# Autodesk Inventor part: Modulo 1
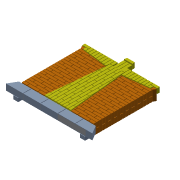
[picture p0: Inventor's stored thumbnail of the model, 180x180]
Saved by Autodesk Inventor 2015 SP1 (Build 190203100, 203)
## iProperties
Created: 2015-04
Part Number: Modulo 1
Material: Generic
Document SubType Name: Modeling
Designer: treina2
Density: 1 g/cm^3
Appearance: Default
Author: treina2
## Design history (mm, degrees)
sketch "Sketch1"
  geometry: L1 (1091.806, 200)-(1091.806, 440) reference; L2 (1091.806, 440)-(1033.806, 440) reference; L3 (1033.806, 440)-(1033.806, 200) reference; L4 (1033.806, 200)-(1091.806, 200) reference; L5 (1159.806, 200)-(1159.806, 315) reference; L6 (1159.806, 315)-(1101.806, 315) reference; L7 (1101.806, 315)-(1101.806, 200) reference; L8 (1101.806, 200)-(1159.806, 200) reference; L9 (1227.806, 200)-(1227.806, 440) reference; L10 (1227.806, 440)-(1169.806, 440) reference; L11 (1169.806, 440)-(1169.806, 200) reference; L12 (1169.806, 200)-(1227.806, 200) reference; L13 (1024, 200)-(1024, 315) reference; L14 (1024, 315)-(966, 315) reference; L15 (966, 315)-(966, 200) reference; L16 (966, 200)-(1024, 200) reference; L17 (1169.806, 1464.632)-(1169.806, 1450) reference; L18 (1169.806, 1450)-(1171.263, 1450) reference; L19 (1284.348, 315)-(1237.806, 315) reference; L20 (1237.806, 315)-(1237.806, 200) reference; L21 (1237.806, 200)-(1295.806, 200) reference; L22 (1259.439, 565)-(1283.351, 325) reference; L23 (1259.439, 565)-(1237.806, 565) reference; L24 (1237.806, 565)-(1237.806, 325) reference; L25 (1237.806, 325)-(1283.351, 325) reference; L26 (1169.806, 1565)-(1177.128, 1492) reference; L27 (1237.806, 1498.938)-(1295.806, 1505.57) reference; L28 (1295.806, 1505.57)-(1295.806, 1686) reference; L29 (1295.806, 1686)-(1237.806, 1686) reference; L30 (1237.806, 1686)-(1237.806, 1498.938) reference; L31 (1159.806, 325)-(1159.806, 565) reference; L32 (1159.806, 565)-(1101.806, 565) reference; L33 (1101.806, 565)-(1101.806, 325) reference; L34 (1101.806, 325)-(1159.806, 325) reference; L35 (1703.806, 1552.224)-(1703.806, 1686) reference; L36 (1703.806, 1686)-(1645.806, 1686) reference; L37 (1645.806, 1686)-(1645.806, 1545.592) reference; L38 (1024, 325)-(1024, 565) reference; L39 (1024, 565)-(966, 565) reference; L40 (966, 565)-(966, 325) reference; L41 (966, 325)-(1024, 325) reference; L42 (1091.806, 450)-(1091.806, 690) reference; L43 (1091.806, 690)-(1033.806, 690) reference; L44 (1033.806, 690)-(1033.806, 450) reference; L45 (1033.806, 450)-(1091.806, 450) reference; L46 (1227.806, 450)-(1227.806, 690) reference; L47 (1227.806, 690)-(1169.806, 690) reference; L48 (1169.806, 690)-(1169.806, 450) reference; L49 (1169.806, 450)-(1227.806, 450) reference; L50 (1159.806, 575)-(1159.806, 815) reference; L51 (1159.806, 815)-(1101.806, 815) reference; L52 (1101.806, 815)-(1101.806, 575) reference; L53 (1101.806, 575)-(1159.806, 575) reference; L54 (1237.806, 782.132)-(1237.806, 575) reference; L55 (1237.806, 575)-(1258.443, 575) reference; L56 (1024, 575)-(1024, 815) reference; L57 (1024, 815)-(966, 815) reference; L58 (966, 815)-(966, 575) reference; L59 (966, 575)-(1024, 575) reference; L60 (1091.806, 700)-(1091.806, 940) reference; L61 (1091.806, 940)-(1033.806, 940) reference; L62 (1033.806, 940)-(1033.806, 700) reference; L63 (1033.806, 700)-(1091.806, 700) reference; L64 (1227.806, 700)-(1227.806, 882.5) reference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; 1 further point
  constraints: 1754 end point, 397 horizontal, 367 vertical, 18 point on line, 953 other
workplane "Work Plane1"
sketch "Sketch2"
  geometry: L1 (1990, 0)-(1600, 0) reference; L2 (1990, 0)-(1880.303, 190) reference; L3 (1765, 190)-(1880.303, 190) reference; L4 (1600, 190)-(1880.303, 190) reference; L5 (1600, 0)-(1600, 190) reference; L6 (1590, 190)-(1590, 0) reference; L7 (1200, 190)-(1590, 190) reference; L8 (1590, 0)-(1200, 0) reference; L9 (1200, 0)-(1200, 190) reference; L10 (1190, 190)-(1190, 0) reference; L11 (1190, 0)-(800, 0) reference; L12 (800, 190)-(1190, 190) reference; L13 (800, 0)-(800, 190) reference; L14 (790, 190)-(790, 0) reference; L15 (400, 190)-(790, 190) reference; L16 (790, 0)-(400, 0) reference; L17 (400, 0)-(400, 190) reference; L18 (390, 190)-(390, 0) reference; L19 (109.697, 190)-(390, 190) reference; L20 (390, 0)-(0, 0) reference; L21 (0, 0)-(109.697, 190) reference; 1 further point
extrude "Extrusion1" new body sketch "Sketch2" distance "d2" = 140 (= BLOCO_PADRAO_LARG); taper "d3" = 0 deg
extrude "Extrusion2" new body sketch "Sketch2" distance "d4" = 140 (= BLOCO_PADRAO_LARG); taper "d5" = 0 deg
extrude "Extrusion3" new body sketch "Sketch2" distance "d6" = 140 (= BLOCO_PADRAO_LARG); taper "d7" = 0 deg
extrude "Extrusion4" new body sketch "Sketch2" distance "d8" = 140 (= BLOCO_PADRAO_LARG); taper "d9" = 0 deg
extrude "Extrusion5" new body sketch "Sketch2" distance "d10" = 140 (= BLOCO_PADRAO_LARG); taper "d11" = 0 deg
extrude "Extrusion6" new body sketch "Sketch1" distance "d12" = 240 (= TIJOLO_PADRAO_COMP); taper "d13" = 0 deg
extrude "Extrusion7" new body sketch "Sketch1" distance "d14" = 240 (= TIJOLO_PADRAO_COMP); taper "d15" = 0 deg
extrude "Extrusion8" new body sketch "Sketch1" distance "d16" = 115 (= TIJOLO_PADRAO_LARG); taper "d17" = 0 deg
extrude "Extrusion9" new body sketch "Sketch1" distance "d18" = 115 (= TIJOLO_PADRAO_LARG); taper "d19" = 0 deg
extrude "Extrusion10" new body sketch "Sketch1" distance "d20" = 115 (= TIJOLO_PADRAO_LARG); taper "d21" = 0 deg
extrude "Extrusion11" new body sketch "Sketch1" distance "d22" = 115 (= TIJOLO_PADRAO_LARG); taper "d23" = 0 deg
extrude "Extrusion12" new body sketch "Sketch1" distance "d24" = 115 (= TIJOLO_PADRAO_LARG); taper "d25" = 0 deg
extrude "Extrusion13" new body sketch "Sketch1" distance "d26" = 240 (= TIJOLO_PADRAO_COMP); taper "d27" = 0 deg
extrude "Extrusion14" new body sketch "Sketch1" distance "d28" = 115 (= TIJOLO_PADRAO_LARG); taper "d29" = 0 deg
extrude "Extrusion15" new body sketch "Sketch1" distance "d30" = 115 (= TIJOLO_PADRAO_LARG); taper "d31" = 0 deg
extrude "Extrusion16" new body sketch "Sketch1" distance "d32" = 115 (= TIJOLO_PADRAO_LARG); taper "d33" = 0 deg
extrude "Extrusion17" new body sketch "Sketch1" distance "d34" = 115 (= TIJOLO_PADRAO_LARG); taper "d35" = 0 deg
extrude "Extrusion18" new body sketch "Sketch1" distance "d36" = 115 (= TIJOLO_PADRAO_LARG); taper "d37" = 0 deg
extrude "Extrusion19" new body sketch "Sketch1" distance "d38" = 115 (= TIJOLO_PADRAO_LARG); taper "d39" = 0 deg
extrude "Extrusion20" new body sketch "Sketch1" distance "d40" = 115 (= TIJOLO_PADRAO_LARG); taper "d41" = 0 deg
extrude "Extrusion21" new body sketch "Sketch1" distance "d42" = 115 (= TIJOLO_PADRAO_LARG); taper "d43" = 0 deg
extrude "Extrusion22" new body sketch "Sketch1" distance "d44" = 115 (= TIJOLO_PADRAO_LARG); taper "d45" = 0 deg
extrude "Extrusion23" new body sketch "Sketch1" distance "d46" = 115 (= TIJOLO_PADRAO_LARG); taper "d47" = 0 deg
extrude "Extrusion24" new body sketch "Sketch1" distance "d48" = 240 (= TIJOLO_PADRAO_COMP); taper "d49" = 0 deg
extrude "Extrusion25" new body sketch "Sketch1" distance "d50" = 115 (= TIJOLO_PADRAO_LARG); taper "d51" = 0 deg
extrude "Extrusion26" new body sketch "Sketch1" distance "d52" = 115 (= TIJOLO_PADRAO_LARG); taper "d53" = 0 deg
extrude "Extrusion27" new body sketch "Sketch1" distance "d54" = 240 (= TIJOLO_PADRAO_COMP); taper "d55" = 0 deg
extrude "Extrusion28" new body sketch "Sketch1" distance "d56" = 115 (= TIJOLO_PADRAO_LARG); taper "d57" = 0 deg
extrude "Extrusion29" new body sketch "Sketch1" distance "d58" = 115 (= TIJOLO_PADRAO_LARG); taper "d59" = 0 deg
extrude "Extrusion30" new body sketch "Sketch1" distance "d60" = 115 (= TIJOLO_PADRAO_LARG); taper "d61" = 0 deg
extrude "Extrusion31" new body sketch "Sketch1" distance "d62" = 115 (= TIJOLO_PADRAO_LARG); taper "d63" = 0 deg
extrude "Extrusion32" new body sketch "Sketch1" distance "d64" = 115 (= TIJOLO_PADRAO_LARG); taper "d65" = 0 deg
extrude "Extrusion33" new body sketch "Sketch1" distance "d66" = 115 (= TIJOLO_PADRAO_LARG); taper "d67" = 0 deg
extrude "Extrusion34" new body sketch "Sketch1" distance "d68" = 115 (= TIJOLO_PADRAO_LARG); taper "d69" = 0 deg
extrude "Extrusion35" new body sketch "Sketch1" distance "d70" = 115 (= TIJOLO_PADRAO_LARG); taper "d71" = 0 deg
extrude "Extrusion36" new body sketch "Sketch1" distance "d72" = 240 (= TIJOLO_PADRAO_COMP); taper "d73" = 0 deg
extrude "Extrusion37" new body sketch "Sketch1" distance "d74" = 115 (= TIJOLO_PADRAO_LARG); taper "d75" = 0 deg
extrude "Extrusion38" new body sketch "Sketch1" distance "d76" = 115 (= TIJOLO_PADRAO_LARG); taper "d77" = 0 deg
extrude "Extrusion39" new body sketch "Sketch1" distance "d78" = 115 (= TIJOLO_PADRAO_LARG); taper "d79" = 0 deg
extrude "Extrusion40" new body sketch "Sketch1" distance "d80" = 115 (= TIJOLO_PADRAO_LARG); taper "d81" = 0 deg
extrude "Extrusion41" new body sketch "Sketch1" distance "d82" = 115 (= TIJOLO_PADRAO_LARG); taper "d83" = 0 deg
extrude "Extrusion42" new body sketch "Sketch1" distance "d84" = 115 (= TIJOLO_PADRAO_LARG); taper "d85" = 0 deg
extrude "Extrusion43" new body sketch "Sketch1" distance "d86" = 115 (= TIJOLO_PADRAO_LARG); taper "d87" = 0 deg
extrude "Extrusion44" new body sketch "Sketch1" distance "d88" = 240 (= TIJOLO_PADRAO_COMP); taper "d89" = 0 deg
extrude "Extrusion45" new body sketch "Sketch1" distance "d90" = 240 (= TIJOLO_PADRAO_COMP); taper "d91" = 0 deg
extrude "Extrusion46" new body sketch "Sketch1" distance "d92" = 240 (= TIJOLO_PADRAO_COMP); taper "d93" = 0 deg
extrude "Extrusion47" new body sketch "Sketch1" distance "d94" = 240 (= TIJOLO_PADRAO_COMP); taper "d95" = 0 deg
extrude "Extrusion48" new body sketch "Sketch1" distance "d96" = 240 (= TIJOLO_PADRAO_COMP); taper "d97" = 0 deg
extrude "Extrusion49" new body sketch "Sketch1" distance "d98" = 115 (= TIJOLO_PADRAO_LARG); taper "d99" = 0 deg
extrude "Extrusion50" new body sketch "Sketch1" distance "d100" = 115 (= TIJOLO_PADRAO_LARG); taper "d101" = 0 deg
extrude "Extrusion51" new body sketch "Sketch1" distance "d102" = 115 (= TIJOLO_PADRAO_LARG); taper "d103" = 0 deg
extrude "Extrusion52" new body sketch "Sketch1" distance "d104" = 115 (= TIJOLO_PADRAO_LARG); taper "d105" = 0 deg
extrude "Extrusion53" new body sketch "Sketch1" distance "d106" = 115 (= TIJOLO_PADRAO_LARG); taper "d107" = 0 deg
extrude "Extrusion54" new body sketch "Sketch1" distance "d108" = 115 (= TIJOLO_PADRAO_LARG); taper "d109" = 0 deg
extrude "Extrusion55" new body sketch "Sketch1" distance "d110" = 115 (= TIJOLO_PADRAO_LARG); taper "d111" = 0 deg
extrude "Extrusion56" new body sketch "Sketch1" distance "d112" = 115 (= TIJOLO_PADRAO_LARG); taper "d113" = 0 deg
extrude "Extrusion57" new body sketch "Sketch1" distance "d114" = 115 (= TIJOLO_PADRAO_LARG); taper "d115" = 0 deg
extrude "Extrusion58" new body sketch "Sketch1" distance "d116" = 115 (= TIJOLO_PADRAO_LARG); taper "d117" = 0 deg
extrude "Extrusion59" new body sketch "Sketch1" distance "d118" = 115 (= TIJOLO_PADRAO_LARG); taper "d119" = 0 deg
extrude "Extrusion60" new body sketch "Sketch1" distance "d120" = 115 (= TIJOLO_PADRAO_LARG); taper "d121" = 0 deg
extrude "Extrusion61" new body sketch "Sketch1" distance "d122" = 115 (= TIJOLO_PADRAO_LARG); taper "d123" = 0 deg
extrude "Extrusion62" new body sketch "Sketch1" distance "d124" = 115 (= TIJOLO_PADRAO_LARG); taper "d125" = 0 deg
extrude "Extrusion63" new body sketch "Sketch1" distance "d126" = 115 (= TIJOLO_PADRAO_LARG); taper "d127" = 0 deg
extrude "Extrusion64" new body sketch "Sketch1" distance "d128" = 115 (= TIJOLO_PADRAO_LARG); taper "d129" = 0 deg
extrude "Extrusion65" new body sketch "Sketch1" distance "d130" = 115 (= TIJOLO_PADRAO_LARG); taper "d131" = 0 deg
extrude "Extrusion66" new body sketch "Sketch1" distance "d132" = 115 (= TIJOLO_PADRAO_LARG); taper "d133" = 0 deg
extrude "Extrusion67" new body sketch "Sketch1" distance "d134" = 115 (= TIJOLO_PADRAO_LARG); taper "d135" = 0 deg
extrude "Extrusion68" new body sketch "Sketch1" distance "d136" = 115 (= TIJOLO_PADRAO_LARG); taper "d137" = 0 deg
extrude "Extrusion69" new body sketch "Sketch1" distance "d138" = 240 (= TIJOLO_PADRAO_COMP); taper "d139" = 0 deg
extrude "Extrusion70" new body sketch "Sketch1" distance "d140" = 240 (= TIJOLO_PADRAO_COMP); taper "d141" = 0 deg
extrude "Extrusion71" new body sketch "Sketch1" distance "d142" = 240 (= TIJOLO_PADRAO_COMP); taper "d143" = 0 deg
extrude "Extrusion72" new body sketch "Sketch1" distance "d144" = 240 (= TIJOLO_PADRAO_COMP); taper "d145" = 0 deg
extrude "Extrusion73" new body sketch "Sketch1" distance "d146" = 240 (= TIJOLO_PADRAO_COMP); taper "d147" = 0 deg
extrude "Extrusion74" new body sketch "Sketch1" distance "d148" = 240 (= TIJOLO_PADRAO_COMP); taper "d149" = 0 deg
extrude "Extrusion75" new body sketch "Sketch1" distance "d150" = 240 (= TIJOLO_PADRAO_COMP); taper "d151" = 0 deg
extrude "Extrusion76" new body sketch "Sketch1" distance "d152" = 240 (= TIJOLO_PADRAO_COMP); taper "d153" = 0 deg
extrude "Extrusion77" new body sketch "Sketch1" distance "d154" = 240 (= TIJOLO_PADRAO_COMP); taper "d155" = 0 deg
extrude "Extrusion78" new body sketch "Sketch1" distance "d156" = 115 (= TIJOLO_PADRAO_LARG); taper "d157" = 0 deg
extrude "Extrusion79" new body sketch "Sketch1" distance "d158" = 115 (= TIJOLO_PADRAO_LARG); taper "d159" = 0 deg
extrude "Extrusion80" new body sketch "Sketch1" distance "d160" = 115 (= TIJOLO_PADRAO_LARG); taper "d161" = 0 deg
extrude "Extrusion81" new body sketch "Sketch1" distance "d162" = 115 (= TIJOLO_PADRAO_LARG); taper "d163" = 0 deg
extrude "Extrusion82" new body sketch "Sketch1" distance "d164" = 115 (= TIJOLO_PADRAO_LARG); taper "d165" = 0 deg
extrude "Extrusion83" new body sketch "Sketch1" distance "d166" = 115 (= TIJOLO_PADRAO_LARG); taper "d167" = 0 deg
extrude "Extrusion84" new body sketch "Sketch1" distance "d168" = 115 (= TIJOLO_PADRAO_LARG); taper "d169" = 0 deg
extrude "Extrusion85" new body sketch "Sketch1" distance "d170" = 115 (= TIJOLO_PADRAO_LARG); taper "d171" = 0 deg
extrude "Extrusion86" new body sketch "Sketch1" distance "d172" = 115 (= TIJOLO_PADRAO_LARG); taper "d173" = 0 deg
extrude "Extrusion87" new body sketch "Sketch1" distance "d174" = 115 (= TIJOLO_PADRAO_LARG); taper "d175" = 0 deg
extrude "Extrusion88" new body sketch "Sketch1" distance "d176" = 115 (= TIJOLO_PADRAO_LARG); taper "d177" = 0 deg
extrude "Extrusion89" new body sketch "Sketch1" distance "d178" = 115 (= TIJOLO_PADRAO_LARG); taper "d179" = 0 deg
extrude "Extrusion90" new body sketch "Sketch1" distance "d180" = 115 (= TIJOLO_PADRAO_LARG); taper "d181" = 0 deg
pattern_linear "Rectangular Pattern1" dims "d184" = 136 (= 2 x TIJOLO_PADRAO_PROF + 2 x GAP)
pattern_linear "Rectangular Pattern2" dims "d187" = 136 (= 2 x TIJOLO_PADRAO_PROF + 2 x GAP)
pattern_linear "Rectangular Pattern3" dims "d190" = 136 (= 2 x TIJOLO_PADRAO_PROF + 2 x GAP)
extrude "Extrusion91" new body sketch "Sketch1" distance "d191" = 115 (= TIJOLO_PADRAO_LARG); taper "d192" = 0 deg
extrude "Extrusion92" new body sketch "Sketch1" distance "d193" = 115 (= TIJOLO_PADRAO_LARG); taper "d194" = 0 deg
extrude "Extrusion93" new body sketch "Sketch1" distance "d195" = 115 (= TIJOLO_PADRAO_LARG); taper "d196" = 0 deg
extrude "Extrusion94" new body sketch "Sketch1" distance "d197" = 115 (= TIJOLO_PADRAO_LARG); taper "d198" = 0 deg
extrude "Extrusion95" new body sketch "Sketch1" distance "d199" = 115 (= TIJOLO_PADRAO_LARG); taper "d200" = 0 deg
extrude "Extrusion96" new body sketch "Sketch1" distance "d201" = 115 (= TIJOLO_PADRAO_LARG); taper "d202" = 0 deg
extrude "Extrusion97" new body sketch "Sketch1" distance "d203" = 115 (= TIJOLO_PADRAO_LARG); taper "d204" = 0 deg
extrude "Extrusion98" new body sketch "Sketch1" distance "d205" = 115 (= TIJOLO_PADRAO_LARG); taper "d206" = 0 deg
extrude "Extrusion99" new body sketch "Sketch1" distance "d207" = 115 (= TIJOLO_PADRAO_LARG); taper "d208" = 0 deg
extrude "Extrusion100" new body sketch "Sketch1" distance "d209" = 115 (= TIJOLO_PADRAO_LARG); taper "d210" = 0 deg
extrude "Extrusion101" new body sketch "Sketch1" distance "d211" = 115 (= TIJOLO_PADRAO_LARG); taper "d212" = 0 deg
extrude "Extrusion102" new body sketch "Sketch1" distance "d213" = 115 (= TIJOLO_PADRAO_LARG); taper "d214" = 0 deg
extrude "Extrusion103" new body sketch "Sketch1" distance "d215" = 115 (= TIJOLO_PADRAO_LARG); taper "d216" = 0 deg
extrude "Extrusion104" new body sketch "Sketch1" distance "d217" = 115 (= TIJOLO_PADRAO_LARG); taper "d218" = 0 deg
extrude "Extrusion105" new body sketch "Sketch1" distance "d219" = 115 (= TIJOLO_PADRAO_LARG); taper "d220" = 0 deg
extrude "Extrusion106" new body sketch "Sketch1" distance "d221" = 115 (= TIJOLO_PADRAO_LARG); taper "d222" = 0 deg
extrude "Extrusion107" new body sketch "Sketch1" distance "d223" = 115 (= TIJOLO_PADRAO_LARG); taper "d224" = 0 deg
extrude "Extrusion108" new body sketch "Sketch1" distance "d225" = 115 (= TIJOLO_PADRAO_LARG); taper "d226" = 0 deg
extrude "Extrusion109" new body sketch "Sketch1" distance "d227" = 240 (= TIJOLO_PADRAO_COMP); taper "d228" = 0 deg
extrude "Extrusion110" new body sketch "Sketch1" distance "d229" = 240 (= TIJOLO_PADRAO_COMP); taper "d230" = 0 deg
workplane "Work Plane2"
sketch "Sketch3"
  geometry: L1 (898.194, 1575)-(898.194, 1815) reference; L2 (898.194, 1815)-(956.194, 1815) reference; L3 (956.194, 1815)-(956.194, 1575) reference; L4 (956.194, 1575)-(898.194, 1575) reference; L5 (966, 1575)-(966, 1815) reference; L6 (1024, 1575)-(966, 1575) reference; L7 (1024, 1815)-(1024, 1575) reference; L8 (1033.806, 1575)-(1033.806, 1815) reference; L9 (1091.806, 1575)-(1033.806, 1575) reference; L10 (1091.806, 1815)-(1091.806, 1575) reference; L11 (1033.806, 1815)-(1091.806, 1815) reference; L12 (966, 1815)-(1024, 1815) reference; 1 further point
extrude "Extrusion111" new body sketch "Sketch3" distance "d232" = 115 (= AMAR_PADRAO_LARG); taper "d233" = 0 deg
extrude "Extrusion112" new body sketch "Sketch3" distance "d234" = 115 (= AMAR_PADRAO_LARG); taper "d235" = 0 deg
extrude "Extrusion113" new body sketch "Sketch3" distance "d236" = 115 (= AMAR_PADRAO_LARG); taper "d237" = 0 deg
workplane "Work Plane3"
sketch "Sketch4"
  geometry: L1 (1081.579, 1883)-(908.421, 1883) reference; L2 (898.194, 1825)-(908.421, 1883) reference; L3 (898.194, 1825)-(1091.806, 1825) reference; L4 (1091.806, 1825)-(1081.579, 1883) reference; 1 further point
extrude "Extrusion114" new body sketch "Sketch4" distance "d239" = 115 (= AMAR_PADRAO_LARG); taper "d240" = 0 deg
workplane "Work Plane4"
sketch "Sketch5"
  geometry: L1 (1091.806, 200)-(1091.806, 440) reference; L2 (1091.806, 440)-(1033.806, 440) reference; L3 (1033.806, 440)-(1033.806, 200) reference; L4 (1033.806, 200)-(1091.806, 200) reference; L5 (1159.806, 200)-(1159.806, 315) reference; L6 (1159.806, 315)-(1101.806, 315) reference; L7 (1101.806, 315)-(1101.806, 200) reference; L8 (1101.806, 200)-(1159.806, 200) reference; L9 (1227.806, 200)-(1227.806, 440) reference; L10 (1227.806, 440)-(1169.806, 440) reference; L11 (1169.806, 440)-(1169.806, 200) reference; L12 (1169.806, 200)-(1227.806, 200) reference; L13 (1024, 200)-(1024, 315) reference; L14 (1024, 315)-(966, 315) reference; L15 (966, 315)-(966, 200) reference; L16 (966, 200)-(1024, 200) reference; L17 (1169.806, 1464.632)-(1169.806, 1450) reference; L18 (1169.806, 1450)-(1171.263, 1450) reference; L19 (1284.348, 315)-(1237.806, 315) reference; L20 (1237.806, 315)-(1237.806, 200) reference; L21 (1237.806, 200)-(1295.806, 200) reference; L22 (1259.439, 565)-(1283.351, 325) reference; L23 (1259.439, 565)-(1237.806, 565) reference; L24 (1237.806, 565)-(1237.806, 325) reference; L25 (1237.806, 325)-(1283.351, 325) reference; L26 (1169.806, 1565)-(1177.128, 1492) reference; L27 (1237.806, 1498.938)-(1295.806, 1505.57) reference; L28 (1295.806, 1505.57)-(1295.806, 1686) reference; L29 (1295.806, 1686)-(1237.806, 1686) reference; L30 (1237.806, 1686)-(1237.806, 1498.938) reference; L31 (1159.806, 325)-(1159.806, 565) reference; L32 (1159.806, 565)-(1101.806, 565) reference; L33 (1101.806, 565)-(1101.806, 325) reference; L34 (1101.806, 325)-(1159.806, 325) reference; L35 (1703.806, 1552.224)-(1703.806, 1686) reference; L36 (1703.806, 1686)-(1645.806, 1686) reference; L37 (1645.806, 1686)-(1645.806, 1545.592) reference; L38 (1024, 325)-(1024, 565) reference; L39 (1024, 565)-(966, 565) reference; L40 (966, 565)-(966, 325) reference; L41 (966, 325)-(1024, 325) reference; L42 (1091.806, 450)-(1091.806, 690) reference; L43 (1091.806, 690)-(1033.806, 690) reference; L44 (1033.806, 690)-(1033.806, 450) reference; L45 (1033.806, 450)-(1091.806, 450) reference; L46 (1227.806, 450)-(1227.806, 690) reference; L47 (1227.806, 690)-(1169.806, 690) reference; L48 (1169.806, 690)-(1169.806, 450) reference; L49 (1169.806, 450)-(1227.806, 450) reference; L50 (1159.806, 575)-(1159.806, 815) reference; L51 (1159.806, 815)-(1101.806, 815) reference; L52 (1101.806, 815)-(1101.806, 575) reference; L53 (1101.806, 575)-(1159.806, 575) reference; L54 (1237.806, 782.132)-(1237.806, 575) reference; L55 (1237.806, 575)-(1258.443, 575) reference; L56 (1024, 575)-(1024, 815) reference; L57 (1024, 815)-(966, 815) reference; L58 (966, 815)-(966, 575) reference; L59 (966, 575)-(1024, 575) reference; L60 (1091.806, 700)-(1091.806, 940) reference; L61 (1091.806, 940)-(1033.806, 940) reference; L62 (1033.806, 940)-(1033.806, 700) reference; L63 (1033.806, 700)-(1091.806, 700) reference; L64 (1227.806, 700)-(1227.806, 882.5) reference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; 2 further points
  constraints: 1754 end point, 397 horizontal, 367 vertical, 18 point on line, 953 other
extrude "Extrusion115" new body sketch "Sketch5" distance "d242" = 115 (= AMAR_PADRAO_LARG); taper "d243" = 0 deg
extrude "Extrusion116" new body sketch "Sketch5" distance "d244" = 115 (= AMAR_PADRAO_LARG); taper "d245" = 0 deg
extrude "Extrusion117" new body sketch "Sketch5" distance "d246" = 115 (= AMAR_PADRAO_LARG); taper "d247" = 0 deg
extrude "Extrusion118" new body sketch "Sketch5" distance "d248" = 115 (= AMAR_PADRAO_LARG); taper "d249" = 0 deg
extrude "Extrusion119" new body sketch "Sketch5" distance "d250" = 115 (= AMAR_PADRAO_LARG); taper "d251" = 0 deg
extrude "Extrusion120" new body sketch "Sketch5" distance "d252" = 115 (= AMAR_PADRAO_LARG); taper "d253" = 0 deg
extrude "Extrusion121" new body sketch "Sketch5" distance "d254" = 115 (= AMAR_PADRAO_LARG); taper "d255" = 0 deg
extrude "Extrusion122" new body sketch "Sketch5" distance "d256" = 115 (= AMAR_PADRAO_LARG); taper "d257" = 0 deg
extrude "Extrusion123" new body sketch "Sketch5" distance "d258" = 115 (= AMAR_PADRAO_LARG); taper "d259" = 0 deg
extrude "Extrusion124" new body sketch "Sketch5" distance "d260" = 115 (= AMAR_PADRAO_LARG); taper "d261" = 0 deg
extrude "Extrusion125" new body sketch "Sketch5" distance "d262" = 115 (= AMAR_PADRAO_LARG); taper "d263" = 0 deg
extrude "Extrusion126" new body sketch "Sketch5" distance "d264" = 115 (= AMAR_PADRAO_LARG); taper "d265" = 0 deg
extrude "Extrusion127" new body sketch "Sketch5" distance "d266" = 115 (= AMAR_PADRAO_LARG); taper "d267" = 0 deg
extrude "Extrusion128" new body sketch "Sketch5" distance "d268" = 115 (= AMAR_PADRAO_LARG); taper "d269" = 0 deg
extrude "Extrusion129" new body sketch "Sketch5" distance "d270" = 115 (= AMAR_PADRAO_LARG); taper "d271" = 0 deg
extrude "Extrusion130" new body sketch "Sketch5" distance "d272" = 115 (= AMAR_PADRAO_LARG); taper "d273" = 0 deg
extrude "Extrusion131" new body sketch "Sketch5" distance "d274" = 115 (= AMAR_PADRAO_LARG); taper "d275" = 0 deg
extrude "Extrusion132" new body sketch "Sketch5" distance "d276" = 115 (= AMAR_PADRAO_LARG); taper "d277" = 0 deg
extrude "Extrusion133" new body sketch "Sketch5" distance "d278" = 115 (= AMAR_PADRAO_LARG); taper "d279" = 0 deg
extrude "Extrusion134" new body sketch "Sketch5" distance "d280" = 115 (= AMAR_PADRAO_LARG); taper "d281" = 0 deg
extrude "Extrusion135" new body sketch "Sketch5" distance "d282" = 115 (= AMAR_PADRAO_LARG); taper "d283" = 0 deg
extrude "Extrusion136" new body sketch "Sketch5" distance "d284" = 115 (= AMAR_PADRAO_LARG); taper "d285" = 0 deg
extrude "Extrusion137" new body sketch "Sketch5" distance "d286" = 115 (= AMAR_PADRAO_LARG); taper "d287" = 0 deg
extrude "Extrusion138" new body sketch "Sketch5" distance "d288" = 115 (= AMAR_PADRAO_LARG); taper "d289" = 0 deg
extrude "Extrusion139" new body sketch "Sketch5" distance "d290" = 115 (= AMAR_PADRAO_LARG); taper "d291" = 0 deg
extrude "Extrusion140" new body sketch "Sketch5" distance "d292" = 115 (= AMAR_PADRAO_LARG); taper "d293" = 0 deg
extrude "Extrusion141" new body sketch "Sketch5" distance "d294" = 115 (= AMAR_PADRAO_LARG); taper "d295" = 0 deg
extrude "Extrusion142" new body sketch "Sketch5" distance "d296" = 115 (= AMAR_PADRAO_LARG); taper "d297" = 0 deg
extrude "Extrusion143" new body sketch "Sketch5" distance "d298" = 115 (= AMAR_PADRAO_LARG); taper "d299" = 0 deg
extrude "Extrusion144" new body sketch "Sketch5" distance "d300" = 115 (= AMAR_PADRAO_LARG); taper "d301" = 0 deg
extrude "Extrusion145" new body sketch "Sketch5" distance "d302" = 115 (= AMAR_PADRAO_LARG); taper "d303" = 0 deg
extrude "Extrusion146" new body sketch "Sketch5" distance "d304" = 115 (= AMAR_PADRAO_LARG); taper "d305" = 0 deg
extrude "Extrusion147" new body sketch "Sketch5" distance "d306" = 115 (= AMAR_PADRAO_LARG); taper "d307" = 0 deg
extrude "Extrusion148" new body sketch "Sketch5" distance "d308" = 115 (= AMAR_PADRAO_LARG); taper "d309" = 0 deg
extrude "Extrusion149" new body sketch "Sketch5" distance "d310" = 115 (= AMAR_PADRAO_LARG); taper "d311" = 0 deg
extrude "Extrusion150" new body sketch "Sketch5" distance "d312" = 115 (= AMAR_PADRAO_LARG); taper "d313" = 0 deg
extrude "Extrusion151" new body sketch "Sketch5" distance "d314" = 115 (= AMAR_PADRAO_LARG); taper "d315" = 0 deg
extrude "Extrusion152" new body sketch "Sketch5" distance "d316" = 115 (= AMAR_PADRAO_LARG); taper "d317" = 0 deg
extrude "Extrusion153" new body sketch "Sketch5" distance "d318" = 115 (= AMAR_PADRAO_LARG); taper "d319" = 0 deg
extrude "Extrusion154" new body sketch "Sketch5" distance "d320" = 115 (= AMAR_PADRAO_LARG); taper "d321" = 0 deg
extrude "Extrusion155" new body sketch "Sketch5" distance "d322" = 115 (= AMAR_PADRAO_LARG); taper "d323" = 0 deg
extrude "Extrusion156" new body sketch "Sketch5" distance "d324" = 115 (= AMAR_PADRAO_LARG); taper "d325" = 0 deg
extrude "Extrusion157" new body sketch "Sketch5" distance "d326" = 115 (= AMAR_PADRAO_LARG); taper "d327" = 0 deg
extrude "Extrusion158" new body sketch "Sketch5" distance "d328" = 115 (= AMAR_PADRAO_LARG); taper "d329" = 0 deg
extrude "Extrusion159" new body sketch "Sketch5" distance "d330" = 115 (= AMAR_PADRAO_LARG); taper "d331" = 0 deg
extrude "Extrusion160" new body sketch "Sketch5" distance "d332" = 115 (= AMAR_PADRAO_LARG); taper "d333" = 0 deg
extrude "Extrusion161" new body sketch "Sketch5" distance "d334" = 115 (= AMAR_PADRAO_LARG); taper "d335" = 0 deg
extrude "Extrusion162" new body sketch "Sketch5" distance "d336" = 115 (= AMAR_PADRAO_LARG); taper "d337" = 0 deg
extrude "Extrusion163" new body sketch "Sketch5" distance "d338" = 115 (= AMAR_PADRAO_LARG); taper "d339" = 0 deg
extrude "Extrusion164" new body sketch "Sketch5" distance "d340" = 115 (= AMAR_PADRAO_LARG); taper "d341" = 0 deg
extrude "Extrusion165" new body sketch "Sketch5" distance "d342" = 115 (= AMAR_PADRAO_LARG); taper "d343" = 0 deg
extrude "Extrusion166" new body sketch "Sketch5" distance "d344" = 115 (= AMAR_PADRAO_LARG); taper "d345" = 0 deg
extrude "Extrusion167" new body sketch "Sketch5" distance "d346" = 115 (= AMAR_PADRAO_LARG); taper "d347" = 0 deg
extrude "Extrusion168" new body sketch "Sketch5" distance "d348" = 115 (= AMAR_PADRAO_LARG); taper "d349" = 0 deg
extrude "Extrusion169" new body sketch "Sketch5" distance "d350" = 115 (= AMAR_PADRAO_LARG); taper "d351" = 0 deg
extrude "Extrusion170" new body sketch "Sketch5" distance "d352" = 115 (= AMAR_PADRAO_LARG); taper "d353" = 0 deg
extrude "Extrusion171" new body sketch "Sketch5" distance "d354" = 115 (= AMAR_PADRAO_LARG); taper "d355" = 0 deg
extrude "Extrusion172" new body sketch "Sketch5" distance "d356" = 115 (= AMAR_PADRAO_LARG); taper "d357" = 0 deg
extrude "Extrusion173" new body sketch "Sketch5" distance "d358" = 115 (= AMAR_PADRAO_LARG); taper "d359" = 0 deg
extrude "Extrusion174" new body sketch "Sketch5" distance "d360" = 115 (= AMAR_PADRAO_LARG); taper "d361" = 0 deg
extrude "Extrusion175" new body sketch "Sketch5" distance "d362" = 115 (= AMAR_PADRAO_LARG); taper "d363" = 0 deg
extrude "Extrusion176" new body sketch "Sketch5" distance "d364" = 115 (= AMAR_PADRAO_LARG); taper "d365" = 0 deg
extrude "Extrusion177" new body sketch "Sketch5" distance "d366" = 115 (= AMAR_PADRAO_LARG); taper "d367" = 0 deg
extrude "Extrusion178" new body sketch "Sketch5" distance "d368" = 115 (= AMAR_PADRAO_LARG); taper "d369" = 0 deg
extrude "Extrusion179" new body sketch "Sketch5" distance "d370" = 115 (= AMAR_PADRAO_LARG); taper "d371" = 0 deg
extrude "Extrusion180" new body sketch "Sketch5" distance "d372" = 115 (= AMAR_PADRAO_LARG); taper "d373" = 0 deg
extrude "Extrusion181" new body sketch "Sketch5" distance "d374" = 115 (= AMAR_PADRAO_LARG); taper "d375" = 0 deg
extrude "Extrusion182" new body sketch "Sketch5" distance "d376" = 115 (= AMAR_PADRAO_LARG); taper "d377" = 0 deg
workplane "Work Plane5"
sketch "Sketch6"
  geometry: L1 (-167.194, 1492)-(-282.194, 1492); L2 (-282.194, 1492)-(-282.194, 1550); L3 (-282.194, 1550)-(-167.194, 1550); L4 (-167.194, 1550)-(-167.194, 1492); 1 further point
  constraints: 8 end point, 2 parallel, 1 horizontal, 1 perpendicular
  dimensions: "d379" = 58 distance of L3.end L1.start (= TIJOLO_PADRAO_PROF); "d380" = 115 distance of L1.start L1.end (= TIJOLO_PADRAO_LARG)
extrude "Extrusion183" new body sketch "Sketch6" distance "d381" = 115 (= AMAR_PADRAO_LARG); taper "d382" = 0 deg
pattern_linear "Rectangular Pattern4" dims "d385" = 136 (= 2 x TIJOLO_PADRAO_PROF + 2 x GAP)
sketch "Sketch7"
  geometry: L1 (-1822.806, 1492)-(-1707.806, 1492); L2 (-1707.806, 1492)-(-1707.806, 1550); L3 (-1707.806, 1550)-(-1822.806, 1550); L4 (-1822.806, 1550)-(-1822.806, 1492); 1 further point
  constraints: 8 end point, 2 parallel, 1 horizontal, 1 perpendicular
  dimensions: "d386" = 115 distance of L2.end L3.end (= TIJOLO_PADRAO_LARG); "d387" = 58 distance of L3.end L1.start (= TIJOLO_PADRAO_PROF)
extrude "Extrusion184" new body sketch "Sketch7" distance "d388" = 115 (= AMAR_PADRAO_LARG); taper "d389" = 0 deg
pattern_linear "Rectangular Pattern5" dims "d392" = 136 (= 2 x TIJOLO_PADRAO_PROF + 2 x GAP)
workplane "Work Plane6"
sketch "Sketch8"
  geometry: L1 (0, 0)-(0, -240) reference; L2 (115, -240)-(0, -240); L3 (0, -240)-(0, -160); L4 (0, -160)-(115, -160); L5 (115, -160)-(115, -240); L6 (222.806, -150)-(-167.194, -150) reference; 1 further point
  constraints: 8 end point, 2 parallel, 1 horizontal, 1 perpendicular, 1 point on line
  dimensions: "d394" = 10 distance between parallel lines of L6 L4
extrude "Extrusion185" new body sketch "Sketch8" stored distance "d395" = 115 (= AMAR_PADRAO_LARG); taper "d396" = 0 deg
sketch "Sketch9"
  geometry: L1 (1540.611, 0)-(1540.611, -240) reference; L2 (1655.611, -240)-(1540.611, -240); L3 (1540.611, -240)-(1540.611, -160); L4 (1540.611, -160)-(1655.611, -160); L5 (1655.611, -160)-(1655.611, -240); L6 (1822.806, -150)-(1432.806, -150) reference; 1 further point
  constraints: 8 end point, 2 parallel, 1 horizontal, 1 perpendicular, 1 point on line
  dimensions: "d397" = 10 distance between parallel lines of L6 L4
extrude "Extrusion186" new body sketch "Sketch9" stored distance "d398" = 115 (= AMAR_PADRAO_LARG); taper "d399" = 0 deg
sketch "Sketch10"
  geometry: L1 (-10, 0)-(-400, 0) reference; L2 (-10, -140)-(-400, -140) reference; L3 (-1050, -10)-(640, -10); L4 (640, -10)-(640, -130); L5 (640, -130)-(-1050, -130); L6 (-1050, -130)-(-1050, -10); L7 (-1200, 0)-(-1200, -140) reference; L8 (790, 0)-(790, -140) reference; 1 further point
  constraints: 8 end point, 2 parallel, 1 horizontal, 1 perpendicular
  dimensions: "d400" = 10 distance between parallel lines of L1 L3; "d401" = 10 distance between parallel lines of L5 L2 (= d400); "d402" = 150 distance between parallel lines of L8 L4; "d403" = 150 distance between parallel lines of L7 L6 (= d402)
extrude "Extrusion187" new body sketch "Sketch10" distance "d404" = 190; taper "d405" = 0 deg
sketch "Sketch11"
  geometry: L1 (105.855, -10)-(247.806, -10) reference; L2 (-108.194, 95)-(-166.194, 95) reference; L3 (612.806, 10)-(-1022.806, 10); L4 (-1022.806, 10)-(-1022.806, 85); L5 (-1022.806, 85)-(612.806, 85); L6 (612.806, 85)-(612.806, 10); L7 (390, 0)-(0, 0) reference; L8 (622.806, -10)-(622.806, 230) reference; L9 (-1032.806, -10)-(-1032.806, 230) reference; 1 further point
  constraints: 8 end point, 2 parallel, 1 horizontal, 1 perpendicular
  dimensions: "d406" = 10 distance between parallel lines of L7 L3; "d407" = 10 distance between parallel lines of L2 L5 (= d406); "d408" = 10 distance between parallel lines of L9 L4 (= d406); "d409" = 10 distance between parallel lines of L8 L6 (= d406)
extrude "Extrusion188" join sketch "Sketch11" distance "d410" = 1481; taper "d411" = 0 deg
sketch "Sketch12"
  geometry: L1 (-108.194, -5)-(-108.194, 110) reference; L2 (-301.806, -5)-(-301.806, 110) reference; L3 (612.806, 85)-(-1022.806, 85) reference; L4 (-1022.806, 10)-(612.806, 10) reference; L5 (-1050, 10)-(640, 10) reference; L6 (-118.194, 10)-(-291.806, 10); L7 (-291.806, 10)-(-291.806, 85); L8 (-291.806, 85)-(-118.194, 85); L9 (-118.194, 85)-(-118.194, 10); 1 further point
  constraints: 8 end point, 2 parallel, 2 point on line, 1 horizontal, 1 perpendicular
  dimensions: "d412" = 10 distance between parallel lines of L7 L2; "d413" = 10 distance between parallel lines of L1 L9 (= d412)
extrude "Extrusion189" join sketch "Sketch12" distance "d414" = 155; taper "d415" = 0 deg
sketch "Sketch13"
  geometry: L1 (105, 1360)-(-10, 1360) reference; L2 (105, 1302)-(105, 1360) reference; L3 (-10, 1360)-(-10, 1302) reference; L4 (1645.611, 1360)-(1530.611, 1360) reference; L5 (1645.611, 1302)-(1645.611, 1360) reference; L6 (1530.611, 1360)-(1530.611, 1302) reference; L7 (0, 0)-(0, 1481) reference; L8 (1635.611, 0)-(1635.611, 1481) reference; L9 (0, 0)-(95, 0); L10 (95, 0)-(95, 1360); L11 (95, 1360)-(0, 1360); L12 (0, 1360)-(0, 0); L13 (1635.611, 0)-(1540.611, 0); L14 (1540.611, 0)-(1540.611, 1360); L15 (1540.611, 1360)-(1635.611, 1360); L16 (1635.611, 1360)-(1635.611, 0); 1 further point
  constraints: 16 end point, 4 parallel, 2 horizontal, 2 perpendicular, 2 point on line
  dimensions: "d416" = 10 distance between parallel lines of L14 L6; "d417" = 10 distance between parallel lines of L2 L10 (= d416)
extrude "Extrusion190" join sketch "Sketch13" distance "d418" = 140; taper "d419" = 0 deg
node "M1.1"
node "M1.6"
node "M1.5"
node "M1.2"
node "M1.3"
node "M1.4"
node "M1.7"
node "M1.8"
node "M1.9"
node "M1.10"
node "M1.11"
node "M1.12"
node "M1.13"
node "M1.14"
node "M1.15"
node "M1.16"
node "M1.17"
node "M1.18"
node "M1.19"
node "M1.20"
node "M1.21"
node "M1.22"
node "M1.23"
node "M1.24"
node "M1.25"
node "M1.26"
node "M1.27"
node "M1.28"
node "M1.29"
node "M1.30"
node "M1.31"
node "M1.32"
node "M1.33"
node "M1.34"
node "M1.35"
node "M1.36"
node "M1.37"
node "M1.38"
node "M1.39"
node "M1.40"
node "M1.41"
node "M1.42"
node "M1.43"
node "M1.44"
node "M1.45"
node "M1.46"
node "M1.47"
node "M1.48"
node "M1.49"
node "M1.50"
node "M1.51"
node "M1.52"
node "M1.53"
node "M1.54"
node "M1.55"
node "M1.56"
node "M1.57"
node "M1.58"
node "M1.59"
node "M1.60"
node "M1.61"
node "M1.62"
node "M1.63"
node "M1.64"
node "M1.65"
node "M1.66"
node "M1.67"
node "M1.68"
node "M1.69"
node "M1.70"
node "M1.71"
node "M1.72"
node "M1.73"
node "M1.74"
node "M1.75"
node "M1.76"
node "M1.77"
node "M1.78"
node "M1.79"
node "M1.80"
node "M1.81"
node "M1.82"
node "M1.83"
node "M1.84"
node "M1.85"
node "M1.86"
node "M1.87"
node "M1.88"
node "M1.89"
node "M1.90"
feature "Pattern of M1.90:1"
node "M1.91"
feature "Pattern of M1.90:2"
node "M1.92"
feature "Pattern of M1.90:3"
node "M1.93"
feature "Pattern of M1.90:4"
node "M1.94"
feature "Pattern of M1.90:5"
node "M1.95"
feature "Pattern of M1.90:6"
node "M1.96"
feature "Pattern of M1.90:7"
node "M1.97"
feature "Pattern of M1.90:8"
node "M1.98"
feature "Pattern of M1.90:9"
node "M1.99"
feature "Pattern of M1.90:10"
node "M1.100"
feature "Pattern of M1.90:11"
node "M1.101"
feature "Pattern of M1.90:12"
node "M1.102"
feature "Pattern of M1.90:13"
node "M1.103"
feature "Pattern of M1.90:14"
node "M1.104"
feature "Pattern of M1.90:15"
node "M1.105"
feature "Pattern of M1.90:16"
node "M1.106"
feature "Pattern of M1.90:17"
node "M1.107"
feature "Pattern of M1.90:18"
node "M1.108"
feature "Pattern of M1.90:19"
node "M1.109"
feature "Pattern of M1.90:20"
node "M1.110"
feature "Pattern of M1.90:21"
node "M1.111"
node "M1.112"
node "M1.113"
node "M1.114"
node "M1.115"
node "M1.116"
node "M1.117"
node "M1.118"
node "M1.119"
node "M1.120"
node "M1.121"
node "M1.122"
node "M1.123"
node "M1.124"
node "M1.125"
node "M1.126"
node "M1.127"
node "M1.128"
node "M1.129"
node "M1.130"
node "M1.131"
node "M1.132"
node "M1.133"
node "M1.134"
node "M1.135"
node "M1.136"
node "M1.137"
node "M1.138"
node "M1.139"
node "M1.140"
node "M1.141"
node "M1.142"
node "M1.143"
node "M1.144"
node "M1.145"
node "M1.146"
node "M1.147"
node "M1.148"
node "M1.149"
node "M1.150"
node "M1.151"
node "M1.152"
node "M1.153"
node "M1.154"
node "M1.155"
node "M1.156"
node "M1.157"
node "M1.158"
node "M1.159"
node "M1.160"
node "M1.161"
node "M1.162"
node "M1.163"
node "M1.164"
node "M1.165"
node "M1.166"
node "M1.167"
node "M1.168"
node "M1.169"
node "M1.170"
node "M1.171"
node "M1.172"
node "M1.173"
node "M1.174"
node "M1.175"
node "M1.176"
node "M1.177"
node "M1.178"
node "M1.179"
node "M1.180"
node "M1.181"
node "M1.182"
node "M1.183"
node "M1.184"
node "M1.185"
node "M1.186"
node "M1.187"
node "M1.188"
node "M1.189"
node "M1.190"
node "M1.191"
node "M1.192"
node "M1.193"
node "M1.194"
node "M1.195"
node "M1.196"
node "M1.197"
node "M1.198"
node "M1.199"
node "M1.200"
node "M1.201"
node "M1.202"
node "M1.203"
node "M1.204"
feature "Pattern of M1.204:22"
node "M1.205"
feature "Pattern of M1.204:23"
node "M1.206"
feature "Pattern of M1.204:24"
node "M1.207"
feature "Pattern of M1.204:25"
node "M1.208"
feature "Pattern of M1.204:26"
node "M1.209"
feature "Pattern of M1.204:27"
node "M1.210"
feature "Pattern of M1.204:28"
node "M1.211"
feature "Pattern of M1.204:29"
node "M1.212"
feature "Pattern of M1.204:30"
node "M1.213"
node "M1.214"
feature "Pattern of M1.214:31"
node "M1.215"
feature "Pattern of M1.214:32"
node "M1.216"
feature "Pattern of M1.214:33"
node "M1.217"
feature "Pattern of M1.214:34"
node "M1.218"
feature "Pattern of M1.214:35"
node "M1.219"
feature "Pattern of M1.214:36"
node "M1.220"
feature "Pattern of M1.214:37"
node "M1.221"
feature "Pattern of M1.214:38"
node "M1.222"
feature "Pattern of M1.214:39"
node "M1.223"
node "M1.224"
node "M1.225"
node "Cimento"
other parameters: "TIJOLO_PADRAO_COMP" = 240 [user parameter; used in 22 equation terms], "TIJOLO_PADRAO_LARG" = 115 [user parameter; used in 85 equation terms], "TIJOLO_PADRAO_PROF" = 58 [user parameter; used in 7 equation terms], "BLOCO_PADRAO_LARG" = 140 [user parameter; used in 5 equation terms], "AMAR_PADRAO_LARG" = 115 [user parameter; used in 76 equation terms], "AMAR_PADRAO_PROF" = 58 [user parameter], "d231" = -5, "d238" = 15
